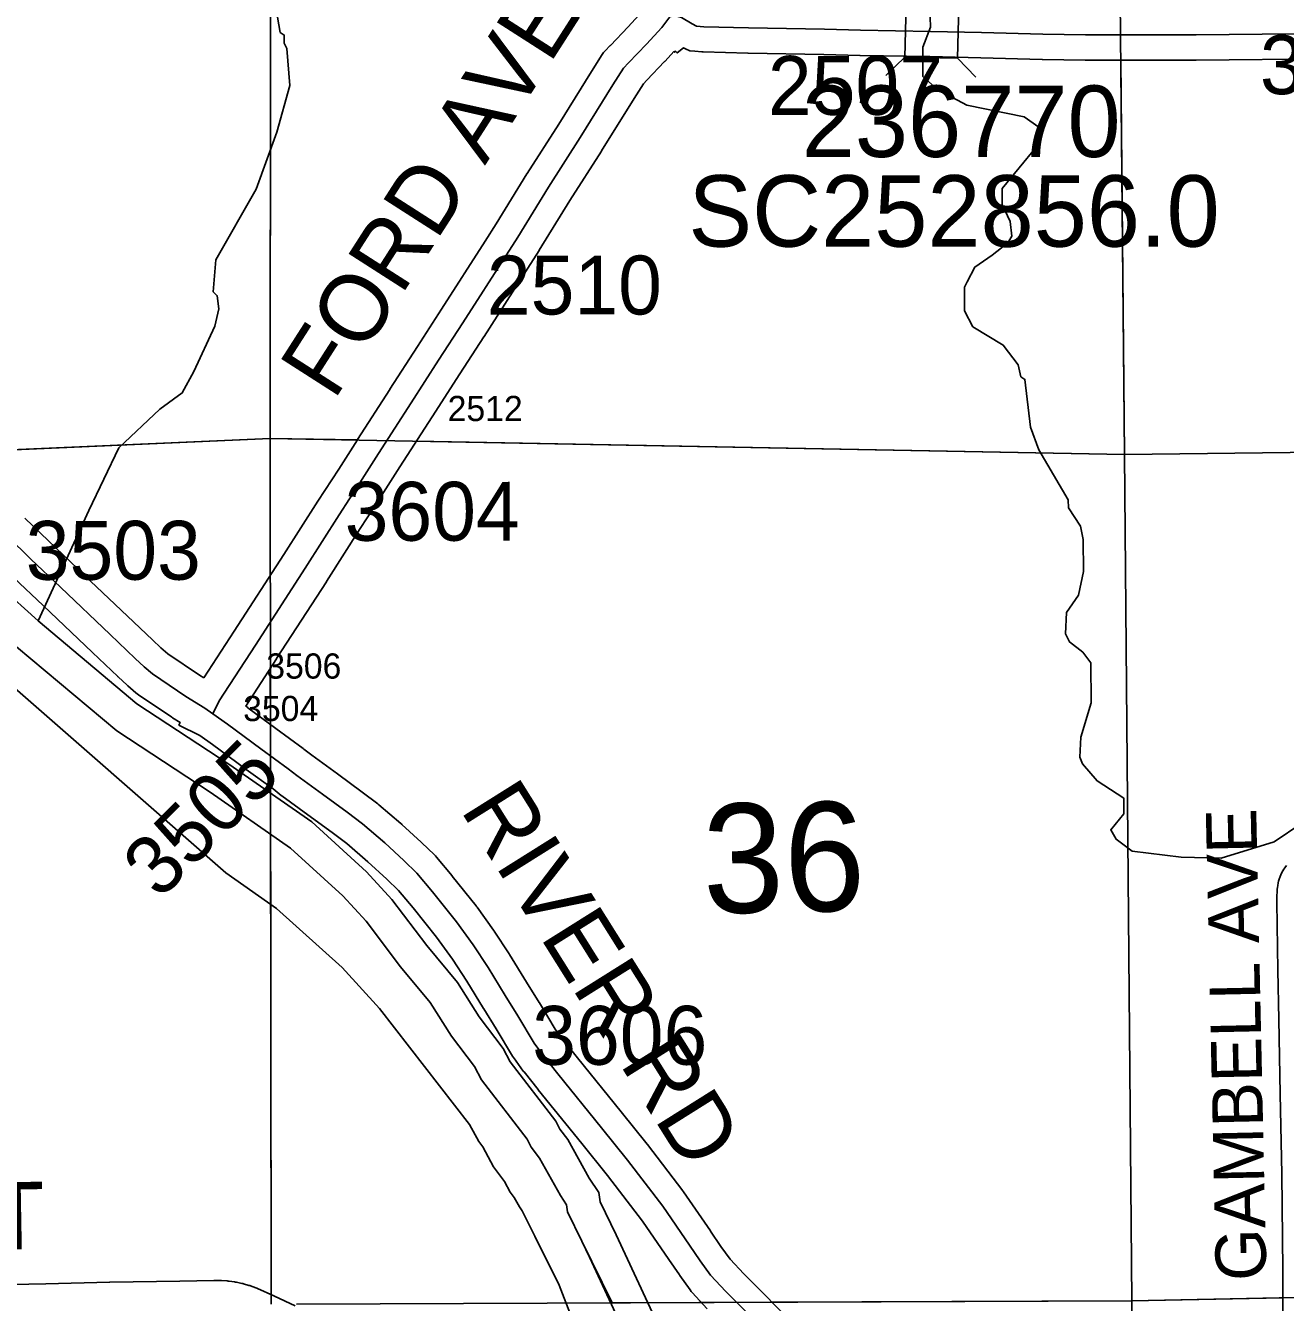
# Model space of a CAD drawing. Extents: x 23.6 to 68.7, y -63 to -29.
# Drawn here: x 37.466 to 38.964, y -51.659 to -50.14 of the extents above; entities that cross this region are included whole.
import ezdxf

# ---------------------------------------------------------------- set-up
doc = ezdxf.new("R2010")
doc.units = 0
for name, color, linetype in [('tdCoHydroRiver', 7, 'Continuous'), ('tdCoSecRdNmbr', 7, 'Continuous'), ('tdCoSecRdTxt', 7, 'Continuous'), ('tdCoSecRteBand', 7, 'Continuous'), ('tdCoSecRteCL', 7, 'Continuous'), ('tdCoSectLine', 7, 'Continuous'), ('tdCoSectLinePart', 7, 'Continuous'), ('tdCoSectNmbr', 7, 'Continuous'), ('tdCoStrucSec', 7, 'Continuous'), ('tdCoStrucSecCoName', 7, 'Continuous'), ('tdCoStrucSecFHWANum', 7, 'Continuous'), ('tdCoSurfGravel', 7, 'Continuous'), ('tdCoTwpBndry', 7, 'Continuous'), ('tdCoTwpBndryShd', 7, 'Continuous')]:
    doc.layers.add(name, color=color, linetype=linetype)

msp = doc.modelspace()

# ---------------------------------------------------------------- linework, layer by layer
at = {"layer": 'tdCoHydroRiver'}
for points in [[(37.7269, -49.8739), (37.7415, -49.9338), (37.7497, -49.9685), (37.7545, -49.9732), (37.761, -50.0015), (37.7619, -50.1089), (37.7685, -50.1483), (37.7733, -50.1514), (37.7734, -50.1609), (37.7766, -50.1672), (37.7801, -50.2113), (37.7647, -50.2667), (37.74, -50.3348), (37.6918, -50.4188), (37.6889, -50.4567), (37.6937, -50.4614), (37.6954, -50.4772), (37.6908, -50.4978), (37.666, -50.5516), (37.652, -50.577), (37.6253, -50.5962), (37.5768, -50.6423), (37.541, -50.7168), (37.4805, -50.8483)], [(38.9836, -51.0888), (38.9507, -51.1111), (38.8877, -51.1306), (38.8403, -51.1294), (38.7819, -51.122), (38.7628, -51.1079), (38.7564, -51.0969), (38.772, -51.0778), (38.7719, -51.0589), (38.7401, -51.0386), (38.7226, -51.0183), (38.7194, -51.0104), (38.7208, -50.9867), (38.7331, -50.9456), (38.7327, -50.8982), (38.7231, -50.8856), (38.7073, -50.8732), (38.7024, -50.8637), (38.7038, -50.8384), (38.7179, -50.8178), (38.7239, -50.7894), (38.7236, -50.7515), (38.7204, -50.7357), (38.706, -50.7137), (38.7059, -50.7043), (38.6707, -50.6446), (38.661, -50.6178), (38.6542, -50.561), (38.6495, -50.5579), (38.6462, -50.5437), (38.6286, -50.5202), (38.5922, -50.4984), (38.5825, -50.4795), (38.5823, -50.4511), (38.5854, -50.4448), (38.5948, -50.4273), (38.6152, -50.413), (38.634, -50.3986), (38.6387, -50.3907), (38.6369, -50.3733), (38.6273, -50.3529), (38.6272, -50.3339), (38.6678, -50.2847), (38.6724, -50.2688), (38.6708, -50.261), (38.6533, -50.2485), (38.5853, -50.2348), (38.5504, -50.2162), (38.533, -50.2005), (38.5327, -50.1658), (38.5419, -50.142), (38.5399, -50.0821)], [(37.4805, -50.8483), (37.436, -50.8076), (37.3105, -50.7092)], [(38.1683, -51.5786), (38.1491, -51.5392), (38.1474, -51.5281), (38.1362, -51.5109), (38.1106, -51.4652), (38.101, -51.4526), (38.0962, -51.4432), (38.042, -51.3726), (38.0339, -51.3569), (38.0052, -51.3192), (37.9796, -51.2784), (37.943, -51.2345), (37.9015, -51.1796), (37.8712, -51.1467), (37.8061, -51.0872), (37.7076, -51.0185), (37.5981, -50.9468), (37.4805, -50.8483)], [(38.0713, -51.5801), (38.0565, -51.5499), (38.0533, -51.5452), (38.0468, -51.534), (38.0419, -51.5277), (38.0354, -51.5149), (38.0224, -51.4975), (38.0096, -51.4739), (38.0048, -51.4676), (37.9936, -51.4472), (37.8868, -51.3091), (37.8422, -51.2606), (37.7643, -51.1902), (37.7039, -51.148), (37.4305, -50.9087), (37.367, -50.8666)], [(38.3124, -51.8286), (38.2852, -51.7861), (38.2757, -51.7783), (38.2693, -51.7642), (38.2533, -51.7422), (38.2309, -51.7029), (38.2229, -51.6887), (38.2165, -51.6824), (38.1683, -51.5786)], [(38.366, -52.0097), (38.3595, -51.9971), (38.326, -51.9625), (38.275, -51.9091), (38.1694, -51.7707), (38.1373, -51.7156), (38.1244, -51.6873), (38.1148, -51.6763), (38.1002, -51.6384), (38.0713, -51.5801)]]:
    msp.add_lwpolyline(points, dxfattribs=at)
at = {"layer": 'tdCoSecRteBand'}
for points in [[(37.6778, -50.9161), (37.7139, -50.8606), (37.7729, -50.7691), (37.8133, -50.7059), (37.8134, -50.7058), (37.8134, -50.7057), (37.8382, -50.6677), (37.8603, -50.6328), (37.8603, -50.6327), (37.8604, -50.6326), (37.8988, -50.5728), (37.8989, -50.5728), (37.8989, -50.5727), (37.9318, -50.5219), (37.9318, -50.5219), (37.9318, -50.5219), (37.9605, -50.4776), (38.0125, -50.3965), (38.0255, -50.3759), (38.0619, -50.3165), (38.0621, -50.3163), (38.0622, -50.316), (38.0999, -50.2572), (38.1388, -50.1949), (38.1389, -50.1948), (38.1389, -50.1947), (38.1516, -50.1747), (38.1531, -50.1722), (38.1551, -50.17), (38.1611, -50.1638), (38.1611, -50.1637), (38.1612, -50.1636), (38.1823, -50.1417), (38.1994, -50.123)], [(39.0154, -50.1796), (38.858, -50.1811), (38.8579, -50.1811), (38.8578, -50.1811), (38.8287, -50.1811), (38.7502, -50.1811), (38.7264, -50.1811), (38.7262, -50.1811), (38.726, -50.1811), (38.6752, -50.1804), (38.675, -50.1804), (38.6747, -50.1804), (38.602, -50.1783), (38.5412, -50.177), (38.4582, -50.1755), (38.4581, -50.1755), (38.4581, -50.1755), (38.4152, -50.1745), (38.325, -50.1729), (38.3249, -50.1729), (38.3248, -50.1729), (38.2717, -50.1714), (38.2709, -50.1714), (38.2702, -50.1713), (38.2615, -50.1707), (38.2556, -50.1702), (38.2504, -50.1676), (38.2483, -50.1666), (38.2405, -50.1726), (38.2387, -50.1704), (38.2377, -50.1718), (38.2367, -50.1711), (38.2264, -50.1824), (38.2261, -50.1827), (38.2258, -50.183), (38.2045, -50.2051), (38.2007, -50.2092), (38.1897, -50.2267), (38.1508, -50.2891), (38.1507, -50.2892), (38.1506, -50.2894), (38.1129, -50.3482), (38.0766, -50.4074), (38.0765, -50.4076), (38.0764, -50.4077), (38.0632, -50.4286), (38.0632, -50.4287), (38.0631, -50.4288), (38.011, -50.51), (38.0109, -50.5101), (38.0109, -50.5102), (37.9821, -50.5545), (37.9493, -50.6053), (37.9109, -50.665), (37.8887, -50.6999), (37.8886, -50.7001), (37.8885, -50.7002), (37.8638, -50.7383), (37.8234, -50.8015), (37.8234, -50.8015), (37.8234, -50.8016), (37.7643, -50.8931), (37.7643, -50.8932), (37.7643, -50.8932), (37.7276, -50.9496), (37.7301, -50.9513), (37.7299, -50.9515), (37.7634, -50.9763), (37.7958, -50.9999), (37.7963, -51.0003), (37.7967, -51.0006), (37.8063, -51.0081), (37.8367, -51.0302), (37.8368, -51.0303), (37.8368, -51.0303), (37.8659, -51.0518), (37.8661, -51.0519), (37.8662, -51.052), (37.8845, -51.0658), (37.8852, -51.0663), (37.8858, -51.0669), (37.9122, -51.0893), (37.9127, -51.0897), (37.9131, -51.0902), (37.9361, -51.1114), (37.9362, -51.1115), (37.9364, -51.1117), (37.9519, -51.1265), (37.9532, -51.1277), (37.9544, -51.1291), (37.9729, -51.1515), (37.973, -51.1517), (37.9731, -51.1518), (38.0017, -51.1873), (38.0022, -51.1879), (38.0027, -51.1886), (38.0224, -51.216), (38.0228, -51.2165), (38.0232, -51.2171), (38.0409, -51.2442), (38.0412, -51.2446), (38.0414, -51.245), (38.0616, -51.2779), (38.0766, -51.302), (38.0767, -51.3022), (38.0768, -51.3024), (38.0956, -51.3338), (38.1057, -51.3477), (38.122, -51.3681), (38.174, -51.4321), (38.1741, -51.4322), (38.1741, -51.4323), (38.2049, -51.4707), (38.2051, -51.471), (38.2053, -51.4712), (38.2475, -51.5262), (38.248, -51.5269), (38.2484, -51.5275), (38.2803, -51.5739), (38.2803, -51.5739), (38.2803, -51.574), (38.2927, -51.5922), (38.3037, -51.6075), (38.32, -51.625), (38.3826, -51.6878)], [(37.4649, -50.7259), (37.4928, -50.753), (37.528, -50.7864), (37.528, -50.7864), (37.528, -50.7865), (37.5868, -50.8425), (37.5868, -50.8425), (37.5868, -50.8425), (37.6166, -50.8709), (37.6267, -50.8803), (37.6349, -50.8873), (37.6726, -50.9128), (37.6778, -50.9161)], [(38.2765, -51.6663), (38.2585, -51.6471), (38.2572, -51.6457), (38.256, -51.644), (38.2437, -51.6268), (38.2435, -51.6265), (38.2433, -51.6262), (38.2307, -51.6078), (38.1994, -51.5621), (38.1579, -51.508), (38.1274, -51.4698), (38.0754, -51.4058), (38.0753, -51.4057), (38.0753, -51.4056), (38.0585, -51.3847), (38.0581, -51.3842), (38.0577, -51.3836), (38.0463, -51.3681), (38.0455, -51.367), (38.0448, -51.3658), (38.0255, -51.3335), (38.0106, -51.3095), (38.0105, -51.3094), (38.0105, -51.3093), (37.9905, -51.2767), (37.9733, -51.2505), (37.9545, -51.2243), (37.9265, -51.1896), (37.9092, -51.1687), (37.8952, -51.1553), (37.8729, -51.1346), (37.8476, -51.1131), (37.8302, -51.1), (37.8013, -51.0787), (37.7706, -51.0564), (37.7702, -51.056), (37.7697, -51.0557), (37.7601, -51.0481), (37.728, -51.0248), (37.7279, -51.0247), (37.7277, -51.0246), (37.6882, -50.9953), (37.6729, -50.9846), (37.6481, -50.9722), (37.6496, -50.9692), (37.6403, -50.9634), (37.6399, -50.9631), (37.6395, -50.9628), (37.5998, -50.936), (37.5984, -50.935), (37.597, -50.9339), (37.5872, -50.9254), (37.5868, -50.9251), (37.5864, -50.9247), (37.5757, -50.9148), (37.5755, -50.9147), (37.5754, -50.9145), (37.5454, -50.8859), (37.4866, -50.8299), (37.4513, -50.7964)], [(38.9616, -51.7467), (38.9612, -51.6419), (38.9611, -51.6202), (38.9598, -51.5063), (38.9579, -51.4108), (38.9579, -51.4107), (38.9579, -51.4107), (38.9564, -51.3222), (38.9552, -51.2636), (38.9552, -51.2635), (38.9552, -51.2635), (38.9537, -51.1828), (38.9537, -51.1822), (38.9537, -51.1815), (38.9538, -51.1764), (38.9539, -51.1758), (38.9539, -51.1752), (38.9542, -51.1704), (38.9544, -51.1674), (38.9545, -51.1652), (38.9549, -51.1631), (38.9555, -51.1598), (38.956, -51.1577), (38.9567, -51.1556), (38.9578, -51.1524), (38.9585, -51.1504), (38.9596, -51.1484), (38.9611, -51.1455), (38.9621, -51.1436), (38.9634, -51.1418), (38.9654, -51.1391)], [(37.4088, -51.6382), (37.4898, -51.6366), (37.5657, -51.6347), (37.5658, -51.6347), (37.566, -51.6347), (37.649, -51.6335), (37.6894, -51.6327), (37.6897, -51.6327), (37.6901, -51.6327), (37.6968, -51.6327), (37.6979, -51.6327), (37.6989, -51.6328), (37.7056, -51.6333), (37.7066, -51.6334), (37.7077, -51.6335), (37.7143, -51.6345), (37.7154, -51.6346), (37.7164, -51.6349), (37.7229, -51.6363), (37.724, -51.6365), (37.725, -51.6368), (37.7314, -51.6387), (37.7324, -51.6389), (37.7334, -51.6393), (37.7397, -51.6416), (37.7407, -51.642), (37.7416, -51.6424), (37.7611, -51.651), (37.7615, -51.6512), (37.7619, -51.6514), (37.7862, -51.6631)]]:
    msp.add_lwpolyline(points, dxfattribs=at)
at = {"layer": 'tdCoSecRteCL'}
for points in [[(37.6883, -50.9587), (37.696, -50.9432), (37.7391, -50.8769), (37.7981, -50.7853), (37.8386, -50.722), (37.8634, -50.6839), (37.8856, -50.6489), (37.9241, -50.589), (37.9569, -50.5382), (37.9857, -50.4938), (38.0378, -50.4126), (38.051, -50.3917), (38.0875, -50.3322), (38.1253, -50.2732), (38.1643, -50.2107), (38.1769, -50.1907), (38.1828, -50.1844), (38.2042, -50.1622), (38.2225, -50.1422), (38.2318, -50.1298)], [(38.2585, -50.1381), (38.2638, -50.1407), (38.2725, -50.1414), (38.3256, -50.1429), (38.4158, -50.1445), (38.4588, -50.1455), (38.5418, -50.147), (38.6028, -50.1483), (38.6756, -50.1504), (38.7264, -50.1511), (38.7502, -50.1511), (38.8287, -50.1511), (38.8578, -50.1511), (39.0151, -50.1496), (39.1792, -50.1472), (39.3189, -50.1455), (39.4496, -50.1437), (39.6071, -50.1422), (39.7561, -50.1393)], [(37.6883, -50.9587), (37.679, -50.9522), (37.6563, -50.938), (37.6166, -50.9112), (37.6067, -50.9027), (37.5961, -50.8928), (37.5661, -50.8642), (37.5073, -50.8082), (37.472, -50.7746), (37.444, -50.7474)], [(38.3613, -51.709), (38.2984, -51.6458), (38.2804, -51.6266), (38.2681, -51.6093), (38.2555, -51.5908), (38.2237, -51.5445), (38.1815, -51.4895), (38.1507, -51.451), (38.0987, -51.3869), (38.0819, -51.3659), (38.0706, -51.3504), (38.0511, -51.3178), (38.036, -51.2937), (38.0158, -51.2606), (37.9981, -51.2335), (37.9783, -51.2061), (37.9497, -51.1706), (37.9312, -51.1482), (37.9157, -51.1334), (37.8928, -51.1122), (37.8664, -51.0897), (37.8481, -51.0759), (37.819, -51.0545), (37.7882, -51.0321), (37.7782, -51.0242), (37.7456, -51.0005), (37.7058, -50.9709), (37.6883, -50.9587)]]:
    msp.add_lwpolyline(points, dxfattribs=at)
at = {"layer": 'tdCoSectLine'}
for points in [[(37.7573, -49.6365), (37.7564, -50.6311)], [(38.7634, -49.6525), (38.7727, -50.6504)], [(36.7702, -50.6749), (37.7564, -50.6311)], [(37.7564, -50.6311), (38.7727, -50.6504)], [(37.7564, -50.6311), (37.7576, -51.6611)], [(38.7727, -50.6504), (39.7253, -50.6386)], [(38.7727, -50.6504), (38.7816, -51.657)], [(38.7816, -51.657), (39.7356, -51.6376)], [(37.7881, -51.6611), (38.7816, -51.657)], [(38.7816, -51.657), (38.7858, -52.6972)]]:
    msp.add_lwpolyline(points, dxfattribs=at)
at = {"layer": 'tdCoSectLinePart'}
for points in [[(37.7573, -49.6666), (37.7564, -50.6311)], [(38.7683, -50.1808), (38.7727, -50.6504)], [(37.3844, -50.6476), (37.7564, -50.6311)], [(37.7564, -50.6311), (37.8598, -50.633)], [(37.7564, -50.6311), (37.7566, -50.7933)], [(37.9303, -50.6344), (38.7727, -50.6504)], [(38.7727, -50.6504), (39.7253, -50.6386)], [(38.7727, -50.6504), (38.7816, -51.657)], [(37.7567, -50.9038), (37.7568, -50.9716)], [(37.7569, -51.0461), (37.7576, -51.6501)], [(38.7816, -51.657), (38.9606, -51.6533)], [(38.3537, -51.6587), (38.7816, -51.657)], [(38.7816, -51.657), (38.7824, -51.8544)]]:
    msp.add_lwpolyline(points, dxfattribs=at)
at = {"layer": 'tdCoStrucSec'}
for p, q in [((38.5116, -50.1776), (38.489, -50.1993)), ((38.5742, -50.179), (38.5958, -50.2016))]:
    msp.add_line(p, q, dxfattribs=at)
msp.add_lwpolyline([(38.5129, -50.1151), (38.5755, -50.1164), (38.5742, -50.179), (38.5116, -50.1776)], close=True, dxfattribs=at)
at = {"layer": 'tdCoSurfGravel'}
for points in [[(37.6883, -50.9587), (37.696, -50.9432), (37.7391, -50.8769), (37.7981, -50.7853), (37.8386, -50.722), (37.8634, -50.6839), (37.8856, -50.6489), (37.9241, -50.589), (37.9569, -50.5382), (37.9857, -50.4938), (38.0378, -50.4126), (38.051, -50.3917), (38.0875, -50.3322), (38.1253, -50.2732), (38.1643, -50.2107), (38.1769, -50.1907), (38.1828, -50.1844), (38.2042, -50.1622), (38.2225, -50.1422), (38.2318, -50.1298), (38.2341, -50.1267), (38.2361, -50.1236)], [(38.2318, -50.1298), (38.2346, -50.1291), (38.2375, -50.1289), (38.2403, -50.1291), (38.2431, -50.1296), (38.2459, -50.1306), (38.2585, -50.1381), (38.2638, -50.1407), (38.2725, -50.1414), (38.3256, -50.1429), (38.4158, -50.1445), (38.4588, -50.1455), (38.5418, -50.147), (38.6028, -50.1483), (38.6756, -50.1504), (38.7264, -50.1511), (38.7502, -50.1511)], [(38.7502, -50.1511), (38.8287, -50.1511), (38.8578, -50.1511), (39.0151, -50.1496), (39.1792, -50.1472), (39.3189, -50.1455), (39.4496, -50.1437), (39.6071, -50.1422), (39.7561, -50.1393)], [(37.6883, -50.9587), (37.679, -50.9522), (37.6563, -50.938), (37.6166, -50.9112), (37.6067, -50.9027), (37.5961, -50.8928), (37.5661, -50.8642), (37.5073, -50.8082), (37.472, -50.7746), (37.444, -50.7474)], [(38.2984, -51.6458), (38.2804, -51.6266), (38.2681, -51.6093), (38.2555, -51.5908), (38.2237, -51.5445), (38.1815, -51.4895), (38.1507, -51.451), (38.0987, -51.3869), (38.0819, -51.3659), (38.0706, -51.3504), (38.0511, -51.3178), (38.036, -51.2937), (38.0158, -51.2606), (37.9981, -51.2335), (37.9783, -51.2061), (37.9497, -51.1706), (37.9312, -51.1482), (37.9157, -51.1334), (37.8928, -51.1122), (37.8664, -51.0897), (37.8481, -51.0759), (37.819, -51.0545), (37.7882, -51.0321), (37.7782, -51.0242), (37.7456, -51.0005), (37.7058, -50.9709), (37.6883, -50.9587)], [(38.7343, -51.9766), (38.7317, -51.9775), (38.728, -51.977), (38.7231, -51.9743), (38.6999, -51.958), (38.6407, -51.9171), (38.5588, -51.8596), (38.4992, -51.8182), (38.4489, -51.7842), (38.4146, -51.76), (38.3983, -51.7474), (38.3867, -51.7363), (38.3613, -51.709), (38.2984, -51.6458)]]:
    msp.add_lwpolyline(points, dxfattribs=at)
at = {"layer": 'tdCoTwpBndry'}
for points in [[(38.7816, -51.657), (38.7727, -50.6504), (38.7683, -50.1811)], [(38.1321, -51.5958), (38.1272, -51.586), (38.1103, -51.5513), (38.109, -51.5427), (38.1018, -51.5316), (38.0769, -51.4873), (38.0669, -51.4741), (38.0621, -51.4647), (38.0078, -51.3941), (37.9998, -51.3784), (37.9722, -51.3421), (37.947, -51.302), (37.9115, -51.2595), (37.8706, -51.2053), (37.8429, -51.1752), (37.7809, -51.1187), (37.6851, -51.0518), (37.5741, -50.9791), (37.4547, -50.8791)], [(38.2786, -51.8502), (38.2548, -51.8132), (38.243, -51.8034), (38.2344, -51.7845), (38.2195, -51.764), (38.196, -51.7227), (38.1907, -51.7134), (38.1831, -51.7059), (38.1363, -51.605), (38.1321, -51.5958)], [(38.3533, -51.6587), (38.7816, -51.657), (38.9609, -51.6533)]]:
    msp.add_lwpolyline(points, dxfattribs=at)
at = {"layer": 'tdCoTwpBndryShd'}
for points in [[(38.629, -40.6849), (38.6311, -41.6817), (38.6617, -42.6826), (38.6662, -43.6771), (38.6815, -44.677), (38.6948, -45.6802), (38.7111, -46.6468), (38.7223, -47.6479), (38.7331, -48.6502), (38.7634, -49.6525), (38.7727, -50.6504), (38.7816, -51.657), (38.7858, -52.6972), (38.8068, -53.6871), (38.8119, -54.6885), (38.8276, -55.6912), (38.8374, -56.6904), (38.8607, -57.6881)], [(37.4547, -50.8791), (37.5741, -50.9791), (37.6851, -51.0518), (37.7809, -51.1187), (37.8429, -51.1752), (37.8706, -51.2053), (37.9115, -51.2595), (37.947, -51.302), (37.9722, -51.3421), (37.9998, -51.3784), (38.0078, -51.3941), (38.0621, -51.4647), (38.0669, -51.4741), (38.0769, -51.4873), (38.1018, -51.5316), (38.109, -51.5427), (38.1103, -51.5513), (38.1272, -51.586), (38.1632, -51.6595), (38.7816, -51.657), (39.7356, -51.6376)]]:
    msp.add_lwpolyline(points, dxfattribs=at)

# ---------------------------------------------------------------- texts
at = {"layer": 'tdCoSecRdNmbr'}
for s, height, rotation, p in [('3005', 0.07, 0.0306, (38.9338, -50.2217)), ('2507', 0.07, 0.0301, (38.3486, -50.2463)), ('2510', 0.07, 0.0299, (38.0143, -50.4838)), ('2512', 0.03, 0.0334, (37.9677, -50.6106)), ('3604', 0.07, 0.0298, (37.8452, -50.7529)), ('3503', 0.07, 0.0295, (37.4659, -50.7993)), ('3506', 0.03, 0.0334, (37.752, -50.9169)), ('3504', 0.03, 0.0334, (37.7245, -50.9674)), ('3505', 0.07, 45.0283, (37.6252, -51.1809)), ('3606', 0.07, 0.0299, (38.0683, -51.3762))]:
    msp.add_text(s, height=height, rotation=rotation, dxfattribs=at).set_placement(p)
at = {"layer": 'tdCoSecRdTxt'}
for s, height, rotation, p in [('FORD AVE', 0.08, 57.3466, (37.8324, -50.5872)), ('RIVER RD', 0.08, 302.1168, (37.9818, -51.0725)), ('GAMBELL AVE', 0.06, 91.2498, (38.9416, -51.6326)), ('280TH ST', 0.08, 0.995, (37.0015, -51.6036))]:
    msp.add_text(s, height=height, rotation=rotation, dxfattribs=at).set_placement(p)
at = {"layer": 'tdCoSectNmbr'}
msp.add_text('36', height=0.13, rotation=1.03, dxfattribs=at).set_placement((38.2719, -51.1962))
at = {"layer": 'tdCoStrucSecCoName'}
msp.add_text('SC252856.0', height=0.085, dxfattribs=at).set_placement((38.254, -50.4031))
at = {"layer": 'tdCoStrucSecFHWANum'}
msp.add_text('236770', height=0.085, dxfattribs=at).set_placement((38.3888, -50.2964))

doc.saveas('drawing.dxf')
